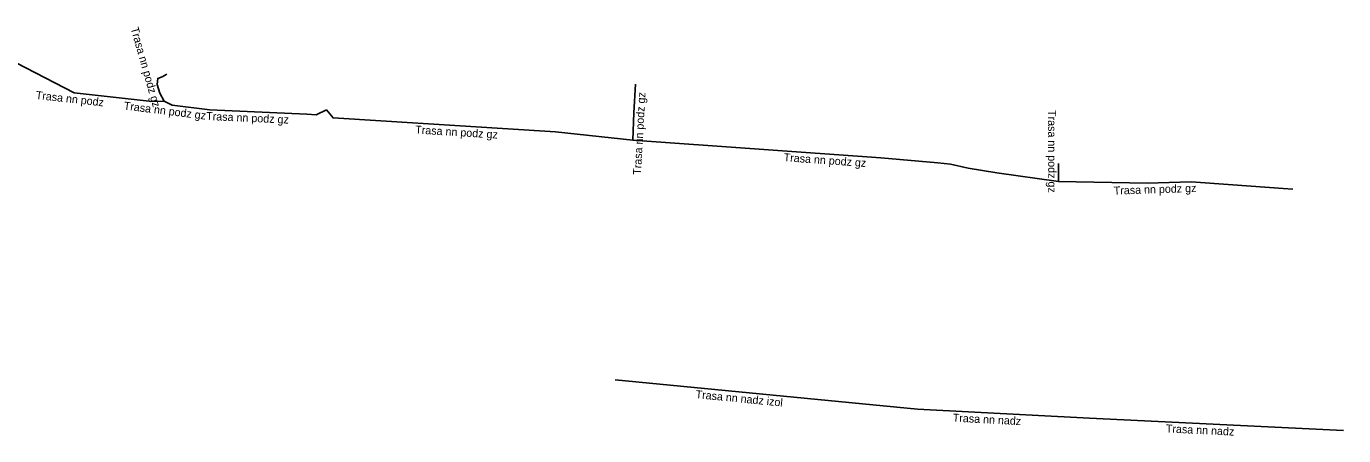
# Model space of a CAD drawing. Extents: x -778200 to -777730, y -1024936 to -1024518.
# Drawn here: x -778102.6 to -778020.3, y -1024720.5 to -1024694.9 of the extents above; entities that cross this region are included whole.
import ezdxf

# ---------------------------------------------------------------- set-up
doc = ezdxf.new("R2010")
doc.units = 0
doc.layers.add('Popiskový text - Ostatní atributy Trasy', color=7, linetype='Continuous')
doc.layers.add('Spojnice NN', color=7, linetype='Continuous')

msp = doc.modelspace()

# ---------------------------------------------------------------- linework, layer by layer
at = {"layer": 'Spojnice NN'}
for points in [[(-778103.254, -1024697.2), (-778099.635, -1024699.073), (-778094.753, -1024699.613), (-778094.01, -1024699.6)], [(-778094.01, -1024699.6), (-778094.29, -1024699.09), (-778094.44, -1024698.56), (-778094.41, -1024698.18), (-778094.13, -1024698.08), (-778093.84, -1024697.92)], [(-778064.735, -1024702.024), (-778064.666, -1024700.32), (-778064.567, -1024698.539)], [(-778091.16, -1024700.13), (-778093.51, -1024699.84), (-778094.01, -1024699.6)], [(-778091.16, -1024700.13), (-778085.093, -1024700.4), (-778084.511, -1024700.462), (-778083.87, -1024700.14)], [(-778064.735, -1024702.024), (-778069.562, -1024701.51), (-778083.456, -1024700.647), (-778083.87, -1024700.14)], [(-778064.735, -1024702.024), (-778049.235, -1024703.127), (-778045.678, -1024703.455), (-778044.892, -1024703.527), (-778043.787, -1024703.791), (-778042, -1024704.069), (-778038.138, -1024704.605)], [(-778038.14, -1024703.483), (-778038.138, -1024704.605)], [(-778038.138, -1024704.605), (-778032.599, -1024704.716), (-778029.857, -1024704.626), (-778027.248, -1024704.818), (-778024.113, -1024705.048), (-778023.515, -1024705.092)], [(-778046.958, -1024718.838), (-778065.841, -1024716.994)], [(-778036.211, -1024719.4), (-778046.958, -1024718.838)], [(-778020.333, -1024720.159), (-778036.211, -1024719.4)]]:
    msp.add_lwpolyline(points, dxfattribs=at)

# ---------------------------------------------------------------- texts
at = {"layer": 'Popiskový text - Ostatní atributy Trasy'}
for s, rotation, p in [('Trasa nn podz gz', 285.80251, (-778096.109, -1024695.05)), ('Trasa nn podz', 353.68815, (-778102.05, -1024699.459)), ('Trasa nn podz gz', 86.81839, (-778064.23, -1024704.205)), ('Trasa nn podz gz', 352.96502, (-778096.554, -1024700.119)), ('Trasa nn podz gz', 357.45184, (-778091.395, -1024700.771)), ('Trasa nn podz gz', 270.10213, (-778038.796, -1024700.152)), ('Trasa nn podz gz', 356.44575, (-778078.34, -1024701.616)), ('Trasa nn podz gz', 355.92962, (-778055.327, -1024703.345)), ('Trasa nn podz gz', 1.87993, (-778034.689, -1024705.435)), ('Trasa nn nadz izol', 354.42252, (-778060.831, -1024718.136)), ('Trasa nn nadz', 357.00652, (-778044.761, -1024719.603)), ('Trasa nn nadz', 357.26323, (-778031.447, -1024720.278))]:
    msp.add_text(s, height=0.5, rotation=rotation, dxfattribs=at).set_placement(p)

doc.saveas('drawing.dxf')
